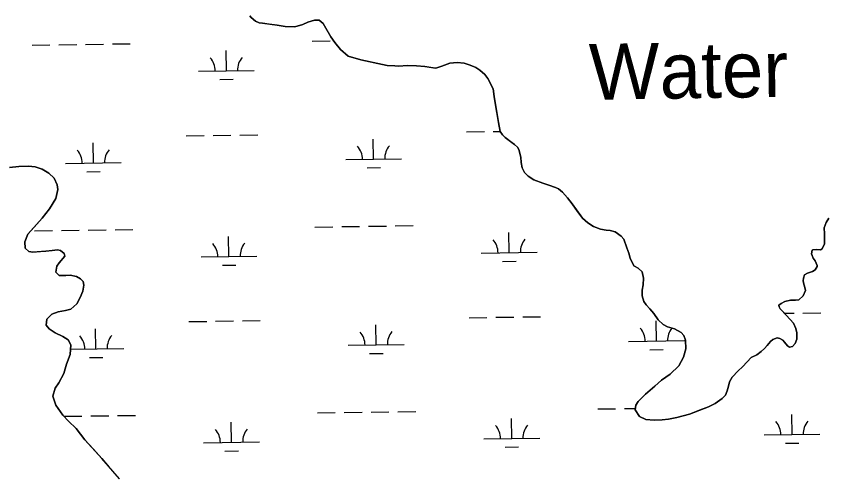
# Model space of a CAD drawing. Extents: x 3767014 to 3805179, y 361544 to 387384.
# Drawn here: x 3775749 to 3777201, y 372013 to 372839 of the extents above; entities that cross this region are included whole.
import ezdxf

# ---------------------------------------------------------------- set-up
doc = ezdxf.new("R2010")
doc.units = 0
for name, color, linetype in [('V-RIVR-IDEN', 7, 'Continuous'), ('V-TOPO-SHOR', 7, 'Continuous'), ('V-WETL-SWMP', 7, 'Continuous')]:
    doc.layers.add(name, color=color, linetype=linetype)

msp = doc.modelspace()

# ---------------------------------------------------------------- linework, layer by layer
at = {"layer": 'V-TOPO-SHOR'}
for points in [[(3776608.237, 372677.242), (3776605.345, 372695.264), (3776603.57, 372708.971), (3776594.044, 372727.862), (3776588.271, 372734.975), (3776579.385, 372742.911), (3776572.409, 372747.695), (3776562.292, 372751.344), (3776551.784, 372755), (3776538.9, 372756.344), (3776525.594, 372755.422), (3776511.76, 372749.739), (3776500.766, 372746.208), (3776491.632, 372747.423), (3776481.019, 372748.969), (3776466.259, 372750.413), (3776449.847, 372750.941), (3776434.118, 372750.052), (3776427.319, 372750.218), (3776413.88, 372751.099), (3776405.227, 372753.012), (3776366.395, 372761.339), (3776343.805, 372767.89), (3776329.881, 372779.41), (3776319.883, 372792.051), (3776312.588, 372802.311), (3776303.802, 372818.064), (3776299.218, 372826.336), (3776291.864, 372831.905), (3776283.66, 372832.404), (3776271.491, 372828.654), (3776262.836, 372824.466), (3776248.315, 372820.356), (3776231.122, 372820.972), (3776216.688, 372823.508), (3776202.248, 372825.261), (3776190.535, 372826.586), (3776184.291, 372827.45), (3776178.073, 372830.268), (3776169.951, 372837.021), (3776167.647, 372840.179)], [(3777147.152, 372272.186), (3777147.002, 372260.851), (3777144.164, 372253.068), (3777139.406, 372248.048), (3777133.914, 372246.558), (3777130.428, 372248.948), (3777125.433, 372255.661), (3777121.959, 372259.224), (3777116.919, 372262.417), (3777112.24, 372263.261), (3777104.379, 372260.236), (3777100.034, 372256.775), (3777094.074, 372249.425), (3777089.316, 372244.403), (3777083.381, 372239.009), (3777075.486, 372233.248), (3777065.648, 372228.293), (3777058.508, 372220.568), (3777049.786, 372211.299), (3777042.268, 372204.361), (3777031.565, 372193.162), (3777026.371, 372184.628), (3777024.704, 372176.831), (3777022.644, 372168.65), (3777019.414, 372160.871), (3777013.473, 372155.086), (3777001.232, 372145.861), (3776989.034, 372139.767), (3776972.924, 372133.723), (3776954.851, 372126.922), (3776932.098, 372120.964), (3776917.196, 372117.64), (3776906.237, 372116.612), (3776891.762, 372116.018), (3776876.92, 372116.995), (3776865.654, 372122.617), (3776857.991, 372134.446), (3776858.886, 372143.035), (3776862.881, 372149.63), (3776875.956, 372162.749), (3776892.952, 372176.993), (3776904.818, 372187.395), (3776920.207, 372198.139), (3776935.657, 372213.574), (3776944.064, 372228.713), (3776948.166, 372243.514), (3776947.591, 372259.161), (3776944.967, 372267.797), (3776940.343, 372272.94), (3776927.916, 372279.358), (3776915.453, 372283.041), (3776908.083, 372287.438), (3776898.809, 372295.769), (3776891.14, 372307.207), (3776883.82, 372315.514), (3776877.262, 372322.245), (3776873.043, 372328.555), (3776870.44, 372338.754), (3776870.182, 372348.923), (3776872.259, 372358.28), (3776872.419, 372370.396), (3776870.221, 372381.764), (3776862.877, 372388.115), (3776856.276, 372391.72), (3776855.506, 372392.512), (3776849.041, 372406.281), (3776846.415, 372414.915), (3776843.026, 372424.736), (3776837.361, 372440.057), (3776832.743, 372445.59), (3776821.897, 372453.16), (3776812.937, 372455.624), (3776805.515, 372456.113), (3776795.375, 372458.2), (3776782.923, 372462.662), (3776772.843, 372469.05), (3776763.178, 372477.388), (3776754.345, 372489.622), (3776744.746, 372503.041), (3776736.29, 372514.098), (3776727.82, 372523.984), (3776720.469, 372529.943), (3776715.028, 372532.36), (3776702.965, 372536.821), (3776692.459, 372540.476), (3776676.507, 372546.549), (3776666.427, 372552.936), (3776659.472, 372559.283), (3776655.677, 372567.934), (3776653.455, 372577.346), (3776653.187, 372586.732), (3776649.461, 372600.855), (3776646.776, 372604.802), (3776641.365, 372609.563), (3776635.172, 372614.335), (3776625.106, 372621.897), (3776620.087, 372626.652), (3776616.259, 372632.96), (3776612.949, 372649.03), (3776610.06, 372667.055), (3776608.237, 372677.242)], [(3775737.55, 372568.231), (3775754.016, 372570.363), (3775771.24, 372570.529), (3775783.36, 372569.587), (3775795.824, 372565.12), (3775807.868, 372558.308), (3775817.148, 372549.576), (3775822.858, 372537.367), (3775823.925, 372529.134), (3775820.191, 372513.137), (3775808.985, 372494.107), (3775795.851, 372477.449), (3775781.554, 372461.589), (3775770.036, 372448.826), (3775764.774, 372435.588), (3775765.409, 372424.23)], [(3777204.58, 372477.863), (3777199.781, 372469.716), (3777196.14, 372460.379), (3777196.783, 372449.815), (3777196.67, 372441.216), (3777196.543, 372431.443), (3777192.515, 372422.503), (3777189.76, 372420.975), (3777181.56, 372421.864), (3777176.078, 372421.156), (3777174.894, 372420.39), (3777173.637, 372413.758), (3777174.767, 372410.617), (3777176.666, 372406.291), (3777180.123, 372401.554), (3777183.528, 372392.908), (3777183.502, 372390.954), (3777180.299, 372385.131), (3777175.177, 372382.072), (3777166.54, 372379.446), (3777161.021, 372376.001), (3777158.989, 372370.163), (3777158.539, 372365.477), (3777159.634, 372359.599), (3777161.146, 372355.669), (3777162.612, 372348.222), (3777158.576, 372338.5), (3777150.666, 372331.568), (3777144.793, 372330.861), (3777135.796, 372330.589), (3777125.603, 372328.375), (3777118.912, 372324.945), (3777114.961, 372321.869), (3777115.707, 372319.122), (3777117.609, 372315.188), (3777121.083, 372311.625), (3777128.798, 372303.705), (3777141.518, 372289.854), (3777145.696, 372280.415), (3777147.152, 372272.186)], [(3775765.409, 372424.23), (3775771.985, 372418.272), (3775779.012, 372417.006), (3775793.115, 372417.996), (3775802.517, 372418.655), (3775813.885, 372420.072), (3775823.292, 372421.123), (3775828.756, 372419.878), (3775834.945, 372414.317), (3775836.448, 372409.601), (3775826.511, 372397.991), (3775822.125, 372391.785), (3775820.416, 372380.849), (3775826.21, 372374.902), (3775837.954, 372375.139), (3775845.789, 372375.819), (3775857.5, 372373.318), (3775864.485, 372368.921), (3775869.12, 372364.166), (3775870.599, 372357.492), (3775868.895, 372346.946), (3775863.66, 372335.666), (3775857.641, 372324.396), (3775847.34, 372314.746), (3775837.525, 372312.526), (3775824.576, 372309.955), (3775813.173, 372305.8), (3775804.055, 372296.918), (3775803.127, 372285.971), (3775808.128, 372279.252), (3775818.997, 372272.457), (3775832.61, 372266.016), (3775842.703, 372259.622), (3775847.286, 372250.95), (3775846.279, 372233.743), (3775839.395, 372216.223), (3775834.871, 372199.451), (3775825.649, 372182.744), (3775818.87, 372173.049), (3775814.772, 372159.012), (3775820.04, 372142.896), (3775833.114, 372125.113), (3775843.145, 372114.023), (3775856.676, 372101.322), (3775872.454, 372080.764), (3775887.501, 372064.128), (3775902.545, 372047.494), (3775916.042, 372032.052), (3775934.554, 372011.068)]]:
    msp.add_lwpolyline(points, dxfattribs=at)
at = {"layer": 'V-WETL-SWMP'}
for p, q in [((3775921.689, 372789.497), (3775953.686, 372789.942)), ((3776279.562, 372794.468), (3776311.559, 372794.913)), ((3775777.703, 372787.497), (3775809.7, 372787.941)), ((3775825.698, 372788.164), (3775857.695, 372788.608)), ((3775873.694, 372788.83), (3775905.69, 372789.275)), ((3776125.69, 372741.584), (3776125.19, 372777.58)), ((3776075.695, 372740.889), (3776175.685, 372742.278)), ((3776113.906, 372725.988), (3776137.903, 372726.321)), ((3776555.752, 372632.115), (3776587.749, 372632.559)), ((3776603.747, 372632.782), (3776616.261, 372632.955)), ((3776053.893, 372625.143), (3776085.889, 372625.588)), ((3776101.888, 372625.81), (3776133.885, 372626.255)), ((3776149.883, 372626.477), (3776181.88, 372626.921)), ((3776389.349, 372583.369), (3776388.849, 372619.365)), ((3775887.49, 372576.397), (3775886.99, 372612.394)), ((3775837.494, 372575.703), (3775937.485, 372577.092)), ((3776339.354, 372582.674), (3776439.344, 372584.063)), ((3775875.705, 372560.801), (3775899.703, 372561.135)), ((3776377.565, 372567.773), (3776401.562, 372568.106)), ((3775830.319, 372455.521), (3775862.316, 372455.965)), ((3775878.314, 372456.187), (3775910.311, 372456.632)), ((3775926.31, 372456.854), (3775958.307, 372457.299)), ((3776284.183, 372461.825), (3776316.18, 372462.27)), ((3776332.179, 372462.492), (3776364.176, 372462.937)), ((3776380.174, 372463.159), (3776412.171, 372463.603)), ((3776428.169, 372463.826), (3776460.166, 372464.27)), ((3775782.324, 372454.854), (3775814.321, 372455.298)), ((3776130.311, 372408.941), (3776129.811, 372444.938)), ((3776632.171, 372415.913), (3776631.671, 372451.909)), ((3776582.175, 372415.218), (3776682.166, 372416.607)), ((3776080.316, 372408.247), (3776180.306, 372409.636)), ((3776620.386, 372400.316), (3776644.384, 372400.65)), ((3776118.526, 372393.345), (3776142.524, 372393.678)), ((3776560.373, 372299.472), (3776592.37, 372299.917)), ((3776608.368, 372300.139), (3776640.365, 372300.583)), ((3776656.364, 372300.805), (3776688.361, 372301.25)), ((3777125.276, 372307.319), (3777142.225, 372307.555)), ((3777158.223, 372307.777), (3777190.22, 372308.221)), ((3776058.513, 372292.501), (3776090.51, 372292.945)), ((3776106.509, 372293.167), (3776138.506, 372293.612)), ((3776154.504, 372293.834), (3776186.501, 372294.279)), ((3776393.97, 372250.726), (3776393.47, 372286.723)), ((3776895.83, 372257.697), (3776895.33, 372293.694)), ((3775892.11, 372243.755), (3775891.61, 372279.751)), ((3776845.834, 372257.003), (3776945.825, 372258.392)), ((3775846.828, 372243.126), (3775942.106, 372244.449)), ((3776343.975, 372250.032), (3776443.965, 372251.421)), ((3776884.045, 372242.101), (3776908.043, 372242.435)), ((3775880.326, 372228.158), (3775904.324, 372228.492)), ((3776382.186, 372235.13), (3776406.183, 372235.463)), ((3776790.664, 372136.154), (3776822.661, 372136.598)), ((3776838.659, 372136.821), (3776858.267, 372137.093)), ((3775835.133, 372122.881), (3775866.937, 372123.322)), ((3775882.935, 372123.545), (3775914.932, 372123.989)), ((3775930.931, 372124.211), (3775962.928, 372124.656)), ((3776288.804, 372129.183), (3776320.801, 372129.627)), ((3776336.799, 372129.849), (3776368.796, 372130.294)), ((3776384.795, 372130.516), (3776416.792, 372130.96)), ((3776432.79, 372131.183), (3776464.787, 372131.627)), ((3777138.651, 372090.241), (3777138.151, 372126.238)), ((3776134.932, 372076.298), (3776134.432, 372112.295)), ((3776636.791, 372083.27), (3776636.291, 372119.266)), ((3776586.796, 372082.575), (3776686.787, 372083.964)), ((3777088.656, 372089.547), (3777188.646, 372090.936)), ((3776084.937, 372075.604), (3776184.927, 372076.993)), ((3776625.007, 372067.673), (3776649.005, 372068.007)), ((3777126.866, 372074.645), (3777150.864, 372074.978)), ((3776123.147, 372060.702), (3776147.145, 372061.035))]:
    msp.add_line(p, q, dxfattribs=at)
for points in [[(3776167.646, 372840.178), (3776169.951, 372837.021), (3776178.073, 372830.268), (3776184.291, 372827.45), (3776190.535, 372826.586), (3776216.689, 372823.507), (3776231.122, 372820.972), (3776248.316, 372820.356), (3776262.835, 372824.466), (3776271.491, 372828.654), (3776283.66, 372832.404), (3776291.864, 372831.905), (3776299.219, 372826.336), (3776312.588, 372802.312), (3776319.882, 372792.051), (3776329.881, 372779.41), (3776343.805, 372767.89), (3776366.395, 372761.338), (3776413.88, 372751.099), (3776427.318, 372750.219), (3776434.118, 372750.052), (3776449.847, 372750.941), (3776466.26, 372750.413), (3776481.019, 372748.969), (3776500.766, 372746.208), (3776511.759, 372749.739), (3776525.595, 372755.422), (3776538.9, 372756.343), (3776551.784, 372755.001), (3776562.292, 372751.345), (3776572.41, 372747.694), (3776579.384, 372742.911), (3776588.272, 372734.975), (3776594.044, 372727.862), (3776603.57, 372708.971), (3776605.346, 372695.265), (3776608.237, 372677.242), (3776610.059, 372667.054), (3776612.95, 372649.031), (3776616.259, 372632.959), (3776620.086, 372626.653), (3776625.106, 372621.896), (3776641.365, 372609.563), (3776646.776, 372604.801), (3776649.461, 372600.856), (3776653.186, 372586.733), (3776653.454, 372577.346), (3776655.676, 372567.934), (3776659.472, 372559.283), (3776666.427, 372552.937), (3776676.508, 372546.549), (3776692.458, 372540.476)], [(3775823.924, 372529.135), (3775822.858, 372537.368), (3775817.147, 372549.576), (3775807.868, 372558.308), (3775795.825, 372565.119), (3775783.359, 372569.587), (3775771.239, 372570.529), (3775754.016, 372570.363), (3775737.55, 372568.23)], [(3775934.553, 372011.068), (3775902.546, 372047.494), (3775872.454, 372080.763), (3775856.677, 372101.322), (3775843.145, 372114.023), (3775833.114, 372125.113), (3775820.04, 372142.896), (3775814.772, 372159.012), (3775818.87, 372173.048), (3775825.65, 372182.743), (3775834.871, 372199.452), (3775839.395, 372216.222), (3775846.278, 372233.744), (3775847.286, 372250.951), (3775842.703, 372259.621), (3775832.611, 372266.016), (3775818.997, 372272.456), (3775808.128, 372279.252), (3775803.128, 372285.971), (3775804.054, 372296.917), (3775813.172, 372305.799), (3775824.576, 372309.955), (3775837.525, 372312.525), (3775847.339, 372314.745), (3775857.641, 372324.395), (3775863.659, 372335.666), (3775868.895, 372346.947), (3775870.599, 372357.492), (3775869.121, 372364.165), (3775864.486, 372368.922), (3775857.499, 372373.319), (3775845.79, 372375.82), (3775837.954, 372375.14), (3775826.21, 372374.902), (3775820.417, 372380.849), (3775822.125, 372391.785), (3775826.512, 372397.99), (3775836.448, 372409.601), (3775834.945, 372414.317), (3775828.755, 372419.878), (3775823.292, 372421.123), (3775813.886, 372420.072), (3775802.517, 372418.656), (3775779.013, 372417.007), (3775771.985, 372418.273), (3775765.409, 372424.23), (3775764.775, 372435.588), (3775770.036, 372448.826), (3775795.851, 372477.45), (3775808.984, 372494.107), (3775820.192, 372513.138), (3775823.924, 372529.135)], [(3776692.458, 372540.476), (3776702.966, 372536.82), (3776715.027, 372532.361), (3776720.469, 372529.944), (3776727.819, 372523.983), (3776736.291, 372514.099), (3776744.747, 372503.041), (3776763.178, 372477.387), (3776772.842, 372469.05), (3776782.924, 372462.663), (3776795.376, 372458.199), (3776805.514, 372456.112), (3776812.936, 372455.624), (3776821.896, 372453.16), (3776832.743, 372445.59), (3776837.362, 372440.056), (3776843.026, 372424.735), (3776846.416, 372414.916), (3776849.04, 372406.281), (3776855.506, 372392.512), (3776856.277, 372391.72), (3776862.877, 372388.115), (3776870.222, 372381.764), (3776872.419, 372370.397), (3776872.26, 372358.279), (3776870.183, 372348.923), (3776870.44, 372338.755), (3776873.044, 372328.556), (3776877.262, 372322.245), (3776883.82, 372315.513), (3776891.139, 372307.207), (3776898.809, 372295.769), (3776908.083, 372287.437), (3776915.453, 372283.04), (3776927.916, 372279.358), (3776940.343, 372272.94), (3776944.967, 372267.797), (3776947.59, 372259.161), (3776948.167, 372243.515), (3776944.064, 372228.713), (3776935.656, 372213.575), (3776920.206, 372198.139), (3776904.818, 372187.394), (3776892.953, 372176.993), (3776875.955, 372162.75), (3776862.881, 372149.629), (3776858.885, 372143.035), (3776857.991, 372134.445), (3776865.655, 372122.616), (3776876.92, 372116.995), (3776891.763, 372116.019), (3776906.237, 372116.611), (3776917.197, 372117.641), (3776932.097, 372120.964), (3776954.851, 372126.921), (3776989.033, 372139.767), (3777001.232, 372145.862), (3777013.473, 372155.085), (3777019.413, 372160.872), (3777022.643, 372168.649), (3777024.705, 372176.832), (3777026.371, 372184.629), (3777031.565, 372193.162), (3777042.267, 372204.36), (3777049.786, 372211.299), (3777065.647, 372228.293), (3777075.486, 372233.247), (3777083.381, 372239.008), (3777089.316, 372244.404), (3777094.073, 372249.424), (3777100.034, 372256.774), (3777104.38, 372260.236), (3777112.239, 372263.261), (3777116.919, 372262.418), (3777121.96, 372259.224), (3777125.432, 372255.66), (3777130.427, 372248.948), (3777133.914, 372246.557), (3777139.407, 372248.048), (3777144.164, 372253.069), (3777147.003, 372260.851), (3777147.151, 372272.187), (3777145.695, 372280.416), (3777141.518, 372289.854), (3777128.798, 372303.704), (3777117.61, 372315.188), (3777115.707, 372319.123), (3777114.961, 372321.869), (3777118.911, 372324.945), (3777125.602, 372328.376), (3777135.796, 372330.589), (3777144.792, 372330.862), (3777150.666, 372331.567), (3777158.576, 372338.501), (3777162.613, 372348.222), (3777161.146, 372355.669), (3777159.634, 372359.599), (3777158.538, 372365.477), (3777158.99, 372370.163), (3777161.021, 372376.001), (3777166.54, 372379.447)], [(3777166.54, 372379.447), (3777175.176, 372382.071), (3777180.298, 372385.131), (3777183.502, 372390.954), (3777183.528, 372392.908), (3777180.122, 372401.554), (3777176.666, 372406.291), (3777174.767, 372410.616), (3777173.636, 372413.759), (3777174.895, 372420.389), (3777176.078, 372421.155), (3777181.561, 372421.865), (3777189.76, 372420.976), (3777192.516, 372422.504), (3777196.543, 372431.443), (3777196.784, 372449.815), (3777196.14, 372460.379), (3777199.781, 372469.715), (3777204.579, 372477.862)]]:
    msp.add_lwpolyline(points, dxfattribs=at)
for centre, start, end in [((3776070.446, 372741.291), 0.024037, 41.567696), ((3776180.921, 372742.826), 140.024034, 181.567692), ((3776334.105, 372583.076), 0.024037, 41.567696), ((3776444.58, 372584.611), 140.024034, 181.567692), ((3775832.245, 372576.105), 0.024037, 41.567696), ((3775942.721, 372577.64), 140.024034, 181.567692), ((3776075.067, 372408.649), 0.024037, 41.567696), ((3776185.542, 372410.183), 140.024034, 181.567692), ((3776576.926, 372415.62), 0.024037, 41.567696), ((3776687.402, 372417.155), 140.024034, 181.567692), ((3775947.341, 372244.997), 140.024034, 181.567692), ((3776338.726, 372250.433), 0.024037, 41.567696), ((3776449.201, 372251.968), 140.024034, 181.567692), ((3776840.585, 372257.405), 0.024037, 41.567696), ((3776951.061, 372258.94), 141.855096, 181.567692), ((3775836.866, 372243.462), 0.024037, 41.567696), ((3777083.407, 372089.949), 0.024037, 41.567696), ((3777193.882, 372091.483), 140.024034, 181.567692), ((3776079.688, 372076.006), 0.024037, 41.567696), ((3776190.163, 372077.54), 140.024034, 181.567692), ((3776581.547, 372082.977), 0.024037, 41.567696), ((3776692.022, 372084.512), 140.024034, 181.567692)]:
    msp.add_arc(centre, 35.246, start, end, dxfattribs=at)

# ---------------------------------------------------------------- texts
at = {"layer": 'V-RIVR-IDEN'}
msp.add_text('Water', height=100, rotation=0.919589, dxfattribs=at).set_placement((3776775.845, 372689.407))

doc.saveas('drawing.dxf')
